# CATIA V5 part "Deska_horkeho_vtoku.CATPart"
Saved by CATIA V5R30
Part number: Deska_horkeho_vtoku
Definition: FH 63_346 446_96.7_IMT2_37_90_0_1730_0
Nomenclature: FH 63_346 446_96.7_IMT2_37_90_0_1730_0
Source: Unknown
Description: PART--DESC
Bounding box of the stored display mesh (mm): x -223 to 223, y -173 to 173, z 0 to 96.7
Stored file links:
  E:\Bakalarka\Model\Forma_v7\Deska_horkeho_vtoku.CATPart
  E:\Bakalarka\Model\Forma_v7\Horky_vtok.CATProduct
  E:\Bakalarka\Model\Sestava_formy_sliderky\Forma_Horky_vtok.CATPart
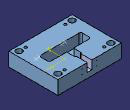
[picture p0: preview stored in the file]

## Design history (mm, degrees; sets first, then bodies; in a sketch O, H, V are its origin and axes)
Body1 "MANIFOLD_SOLID_BREP #3978" (main body)
  Solid1: solid without history
  DatumCurve1 to DatumCurve23
  Sketch1 on face of Solid1, origin (0, 0, 0), H (1, 0, 0), V (0, -1, 0)
    projected arc E1 centre (-100, 102.2143) radius 10.5 from (-110.5, 102.2143) to (-100, 91.7143) ccw from edge of DatumCurve1
    projected line E2 (-110.5, 102.2143) -> (-110.5, 104.2143) from edge of DatumCurve2
    projected arc E3 centre (-100, 104.2143) radius 10.5 from (-100, 114.7143) to (-110.5, 104.2143) ccw from edge of DatumCurve3
    projected line E4 (-81, 91.7143) -> (-100, 91.7143) from edge of DatumCurve4
    projected arc E5 centre (-81, 102.2143) radius 10.5 from (-81, 91.7143) to (-70.5, 102.2143) ccw from edge of DatumCurve5
    projected arc E6 centre (-81, 104.2143) radius 10.5 from (-70.5, 104.2143) to (-81, 114.7143) ccw from edge of DatumCurve6
    projected line E7 (-100, 114.7143) -> (-81, 114.7143) from edge of DatumCurve7
    line L1 (-70.5, 102.2143) -> (-70.5, 104.2143)
    projected line E8 (80, 114.7143) -> (99, 114.7143) from edge of DatumCurve16
    projected arc E9 centre (99, 104.2143) radius 10.5 from (109.5, 104.2143) to (99, 114.7143) ccw from edge of DatumCurve17
    projected line E10 (109.5, 104.2143) -> (109.5, 102.2143) from edge of DatumCurve18
    projected arc E11 centre (99, 102.2143) radius 10.5 from (99, 91.7143) to (109.5, 102.2143) ccw from edge of DatumCurve19
    projected line E12 (99, 91.7143) -> (80, 91.7143) from edge of DatumCurve20
    projected arc E13 centre (80, 102.2143) radius 10.5 from (69.5, 102.2143) to (80, 91.7143) ccw from edge of DatumCurve21
    projected arc E14 centre (80, 104.2143) radius 10.5 from (80, 114.7143) to (69.5, 104.2143) ccw from edge of DatumCurve22
    projected line E15 (69.5, 102.2143) -> (69.5, 104.2143) from edge of DatumCurve23
    vertical: L1 V
  Pocket1: profile Sketch1, direction (0, 0, 1), length 24
  Sketch2 on face of Solid1, origin (0, 0, 96.7), H (1, 0, 0), V (0, 1, 0)
    line L1 (-11, 98) -> (11, 98)
    line L2 (11, 98) -> (11, 173)
    line L3 (11, 173) -> (-11, 173)
    line L4 (-11, 173) -> (-11, 98)
    reference projected line E1 (223, 173) -> (-223, 173) from edge [face of Solid1 | face of Solid1]
    reference projected line E2 (-11, 98) -> (11, 98) from edge [face of Solid1 | face of Solid1]
    reference projected point E3 (11, 98) from edge [face of Solid1 | face of Solid1]
    reference projected point E4 (-11, 98) from edge [face of Solid1 | face of Solid1]
    distance E1 L3 = 0
    distance L1 E2 = 0
    distance L2 E3 = 0
    distance L4 E4 = 0
    horizontal: L1 H, L3 H
    vertical: L2 V, L4 V
  Pocket2: profile Sketch2, direction (0, 0, -1), length 60
  Sketch3 on face of Pocket2 from Sketch2.L2, origin (11, 0, 0), H (0, -1, 0), V (0, 0, 1)
  Pocket3: profile Sketch3, direction (1, 0, 0), length 5
  Sketch4 on face of Pocket3, origin (0, 98, 0), H (-1, 0, 0), V (0, 0, 1)
  Pocket4: profile Sketch4, direction (0, -1, 0), length 5
  Mirror1: of Pocket3, about yz-plane
  Mirror2: of Pocket4, about yz-plane
  Body2 "Result of TapHole"
    Solid2: linked copy from another document
  Assemble1 "TapHoleCapScrew_E1200_2.3": tool Body2
  Body3 "Result of TapHole"
    Solid3: linked copy from another document
  Assemble2 "TapHoleCapScrew_E1200_2.4": tool Body3
  Body4 "Result of TapHole"
    Solid4: linked copy from another document
  Assemble3 "TapHoleCapScrew_E1200_3.1": tool Body4
  Body5 "Result of TapHole"
    Solid5: linked copy from another document
  Assemble4 "TapHoleCapScrew_E1200_3.2": tool Body5
  DatumCurve24 to DatumCurve29
  Sketch5 on end face of Pocket1, origin (0, 0, 24), H (1, 0, 0), V (0, -1, 0)
    reference projected circle E1 centre (76.5, 104.7143) radius 5.5 from edge of DatumCurve26
    reference projected circle E2 centre (102.5, 104.7143) radius 5.5 from edge of DatumCurve27
    point P1 (76.5, 104.7143)
    point P2 (102.5, 104.7143)
    reference projected circle E3 centre (-77.5, 104.7143) radius 5.5 from edge of DatumCurve28
    reference projected circle E4 centre (-103.5, 104.7143) radius 5.5 from edge of DatumCurve29
    point P3 (-103.5, 104.7143)
    point P4 (-77.5, 104.7143)
    concentricity: P1 E1, P2 E2, P3 E4, P4 E3
  Sketch6 on end face of Pocket1, origin (76.5, -104.7143, 24), H (1, 0, 0), V (0, -1, 0)
    point P1 (0, 0)
    reference projected point E1 (0, 0) from Sketch5.P1
    coincidence: E1 P1
  Hole1: placed by Sketch6, at (76.5, -104.7143, 24) direction (0, 0, 1), diameter 4.917, depth 25, V-bottom angle 120, threaded "M6", thread diameter 6, thread depth 20, pitch 1
  Sketch7 on end face of Pocket1, origin (102.5, -104.7143, 24), H (1, 0, 0), V (0, -1, 0)
    point P1 (0, 0)
    reference projected point E1 (0, 0) from Sketch5.P2
    coincidence: E1 P1
  Hole2: placed by Sketch7, at (102.5, -104.7143, 24) direction (0, 0, 1), diameter 4.917, depth 25, V-bottom angle 120, threaded "M6", thread diameter 6, thread depth 20, pitch 1
  DatumCurve30 to DatumCurve37
  Sketch8 on face of Solid1, origin (0, 173, 0), H (-1, 0, 0), V (0, 0, 1)
    reference projected arc E1 centre (51.5, 43.2) radius 3.5 from (48, 43.2) to (55, 43.2) ccw from edge of DatumCurve30
    reference projected arc E4 centre (51.5, 75.2) radius 3.5 from (49.75, 78.2311) to (53.25, 72.1689) ccw from edge of DatumCurve33
    reference projected arc E5 centre (-51.5, 43.2) radius 3.5 from (-55, 43.2) to (-48, 43.2) ccw from edge of DatumCurve34
    reference projected arc E8 centre (-51.5, 75.2) radius 3.5 from (-49.75, 72.1689) to (-53.25, 78.2311) ccw from edge of DatumCurve37
    point P17 (-51.5, 43.2)
    point P18 (-51.5, 75.2)
    point P19 (51.5, 75.2)
    point P20 (51.5, 43.2)
    concentricity: P17 E5, P18 E8, P19 E4, P20 E1
  Sketch9 on face of Solid1, origin (51.5, 173, 75.2), H (1, 0, 0), V (0, 0, -1)
    point P1 (0, 0)
    reference projected point E1 (0, 0) from Sketch8.P18
    coincidence: E1 P1
  Hole3: placed by Sketch9, at (51.5, 173, 75.2) direction (0, -1, 0), diameter 3.242, depth 8, V-bottom angle 120, threaded "M4", thread diameter 4, thread depth 6, pitch 0.7
  Sketch10 on face of Solid1, origin (51.5, 173, 43.2), H (1, 0, 0), V (0, 0, -1)
    point P1 (0, 0)
    reference projected point E1 (0, 0) from Sketch8.P17
    coincidence: E1 P1
  Hole4: placed by Sketch10, at (51.5, 173, 43.2) direction (0, -1, 0), diameter 3.242, depth 8, V-bottom angle 120, threaded "M4", thread diameter 4, thread depth 6, pitch 0.7
  Sketch11 on face of Solid1, origin (-51.5, 173, 75.2), H (1, 0, 0), V (0, 0, -1)
    point P1 (0, 0)
    reference projected point E1 (0, 0) from Sketch8.P19
    coincidence: E1 P1
  Hole5: placed by Sketch11, at (-51.5, 173, 75.2) direction (0, -1, 0), diameter 3.242, depth 8, V-bottom angle 120, threaded "M4", thread diameter 4, thread depth 6, pitch 0.7
  Sketch12 on face of Solid1, origin (-51.5, 173, 43.2), H (1, 0, 0), V (0, 0, -1)
    point P1 (0, 0)
    reference projected point E1 (0, 0) from Sketch8.P20
    coincidence: E1 P1
  Hole6: placed by Sketch12, at (-51.5, 173, 43.2) direction (0, -1, 0), diameter 3.242, depth 8, V-bottom angle 120, threaded "M4", thread diameter 4, thread depth 6, pitch 0.7
  Body6 "Result of TapHole"
    Solid6: linked copy from another document
  Assemble5 "TapHoleCapScrew_E1200_1.5": tool Body6
  Body7 "Result of TapHole"
    Solid7: linked copy from another document
  Assemble6 "TapHoleCapScrew_E1200_1.6": tool Body7
  Body8 "Result of TapHole"
    Solid8: linked copy from another document
  Assemble7 "TapHoleCapScrew_E1200_1.7": tool Body8
  Body9 "Result of TapHole"
    Solid9: linked copy from another document
  Assemble8 "TapHoleCapScrew_E1200_1.8": tool Body9
  DatumCurve38 to DatumCurve41
  Sketch13 on face of Solid1, origin (0, 0, 0), H (1, 0, 0), V (0, -1, 0)
    reference projected circle E1 centre (-77.5, 104.7143) radius 5.5 from edge of DatumCurve38
    reference projected circle E2 centre (-103.5, 104.7143) radius 5.5 from edge of DatumCurve39
    reference projected circle E3 centre (76.5, 104.7143) radius 5.5 from edge of DatumCurve40
    reference projected circle E4 centre (102.5, 104.7143) radius 5.5 from edge of DatumCurve41
    point P1 (-77.5, 104.7143)
    point P2 (-103.5, 104.7143)
    point P3 (76.5, 104.7143)
    point P4 (102.5, 104.7143)
    concentricity: P1 E1, P2 E2, P3 E3, P4 E4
